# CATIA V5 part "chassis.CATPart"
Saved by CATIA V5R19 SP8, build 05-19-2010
Part number: chassis
Bounding box of the stored display mesh (mm): x -57.994 to 177.587, y -4 to 188.1, z -38.5 to 54.38
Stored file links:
  G:\EU_thinkMotion\CFAO_2010\MMS_groupe1\MMS_groupe1\A reprendre\gduval\CFAO kinematic ok\chassis.CATPart
  C:\Users\guillaume\ecole\Cours IFMA\S3\CFAO\brevet Think motion\CATIA\deployable spoiler (EP 2 119 619 A2).CATProduct
  C:\Users\guillaume\ecole\Cours IFMA\S3\CFAO\brevet Think motion\CATIA\skeleton chassis.CATPart
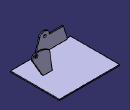
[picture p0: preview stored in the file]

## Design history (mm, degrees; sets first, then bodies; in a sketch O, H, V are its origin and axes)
Body1 (main body)
  Plane1: stored without definition
  Point1: stored without definition
  Point2: stored without definition
  Plane2: stored without definition
  Line1: type Normal, RefPoint Point2, RefSkin Plane2, Start -20, End 20
  Line2: type Normal, RefPoint Point1, RefSkin Plane2, Start -20, End 20
  Point3: stored without definition
  Plane3: stored without definition
  Point4: stored without definition
  Line3: type PtPt, FirstPoint Point4, SecondPoint Point3
  Point5: stored without definition
  Line4: type PtDir, RefPoint Point5, Direction zx-plane, Start -20, End 20
  Plane4: stored without definition
  Point6: stored without definition
  Line5: type Normal, RefPoint Point6, RefSkin Plane4, Start -20, End 20
  Sketch1 on zx-plane, origin (0, 0, 0), H (-1, 0, 0), V (0, 0, 1)
    line L1 (26.2235, 17.8338) -> (42.2146, -34.5)
    point P2 (42.2146, -34.5)
    reference intersected line E1 through (0, -34.5) direction (-1, 0) from Plane1
    line L2 (26.2235, 17.8338) -> (-27.9715, 17.8338)
    point P3 (-27.9715, 17.8338)
    spline S1 through (-27.9715, 17.8338) (-29.1855, 19.9801) (-29.8131, 24.0632) (-30.6294, 28.1144) (-34.4814, 32.2772) (-40.0196, 35.6386) (-46.6437, 37.2027) (-53.108, 36.528) (-59.3226, 33.654) (-63.621, 31.0772) (-67.1277, 25.7733)
    line L3 (-67.1277, 25.7733) -> (-84.0639, -34.5)
    point P4 (-67.1277, 25.7733)
    point P5 (-84.0639, -34.5)
    reference intersected line E2 through (0, -34.5) direction (-1, 0) from Plane1
    line L4 (-84.0639, -34.5) -> (42.2146, -34.5)
    reference intersected line E3 through (0, -34.5) direction (-1, 0) from Plane1
    point P6 (-27.9715, 17.8338)
    point P7 (-67.1277, 25.7733)
    coincidence: P2 E1, P6 P3, P7 P4, P5 E2, L4 E3
    horizontal: L2 H, L4 H
  Pad1: profile Sketch1, direction (0, -1, 0), length 4
  Sketch2 on end face of Pad1, origin (46.744, -4, 20.55), H (1, 0, 0), V (0, 0, 1)
    point P1 (0, 0)
    intersected point E1 (0, 0) from Line4
    coincidence: E1 P1
  Hole1: placed by Sketch2, at (46.744, -4, 20.55) direction (0, 1, 0), diameter 10, through (limit type 6)
  Sketch3 on Plane4, origin (0, 76, 0), H (-1, 0, 0), V (0, 0, 1)
    line L1 (-130.0682, -34.5) -> (-166.2396, 26.9767)
    point P2 (-166.2396, 26.9767)
    line L2 (-130.0682, -34.5) -> (-93.7799, -34.5)
    reference intersected line E1 through (0, -34.5) direction (-1, 0) from Plane1
    spline S1 through (-166.2396, 26.9767) (-170.0746, 33.4945) (-170.0746, 43.013) (-166.2396, 51.1679) (-149.6891, 54.2259) (-136.9475, 54.2259) (-130.0682, 52.9517) (-113.7099, 46.3058) (-103.9459, 39.3141)
    line L3 (-103.9459, 39.3141) -> (-93.7799, -34.5)
    point P4 (-103.9459, 39.3141)
    point P5 (-166.2396, 26.9767)
    point P6 (-170.0746, 33.4945)
    point P7 (-103.9459, 39.3141)
    horizontal: L2 H
    coincidence: L2 E1, P5 P2, P6 L1, P7 P4
  Pad2: profile Sketch3, direction (0, -1, 0), length 4
  Sketch4 on end face of Pad2, origin (156.193, 72, 43.188), H (1, 0, 0), V (0, 0, 1)
    point P1 (0, 0)
    intersected point E1 (0, 0) from Line5
    coincidence: E1 P1
  Hole2: placed by Sketch4, at (156.193, 72, 43.188) direction (0, 1, 0), diameter 13, through (limit type 6)
  Sketch5 on end face of Pad1, origin (0, -4, 0), H (1, 0, 0), V (0, 0, 1)
    line L1 (-57.9936, -34.5) -> (177.5874, -34.5)
    line L2 (177.5874, -34.5) -> (177.5874, -38.5)
    line L3 (177.5874, -38.5) -> (-57.9936, -38.5)
    line L4 (-57.9936, -38.5) -> (-57.9936, -34.5)
    reference projected line E1 (84.0639, -34.5) -> (-42.2146, -34.5) from edge [end face of Pad1 | face of Pad1 from Sketch1.L4]
    distance L3 L1 = 4
    horizontal: L1 H, L3 H
    vertical: L2 V, L4 V
    coincidence: L1 E1
  Pad3: profile Sketch5, direction (0, -1, 0), up to Plane2, offset 35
